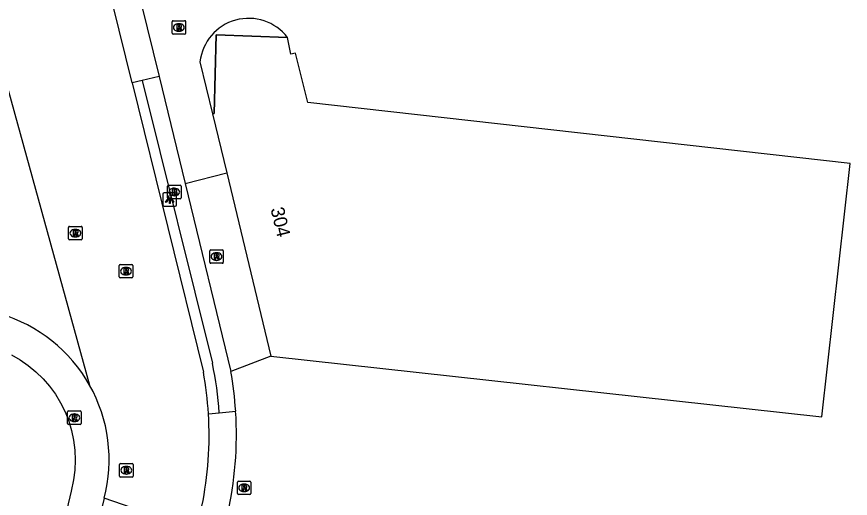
# Model space of a CAD drawing. Extents: x 161389 to 162585, y 388479 to 389761.
# Drawn here: x 162212.3 to 162273.9, y 388784.9 to 388820.5 of the extents above; entities that cross this region are included whole.
import ezdxf

# ---------------------------------------------------------------- set-up
doc = ezdxf.new("R2010")
doc.units = 0
for name, color, linetype in [('IMGEO_Berm_groen', 7, 'Continuous'), ('IMGEO_Brandkraan', 7, 'Continuous'), ('IMGEO_Groenvoorziening', 7, 'Continuous'), ('IMGEO_Lichtpunt', 7, 'Continuous'), ('IMGEO_Pand', 7, 'Continuous'), ('IMGEO_Pand_nummerreeks', 7, 'Continuous'), ('IMGEO_Pand_overbouw', 7, 'Continuous'), ('IMGEO_Rijbaan_lokaal_gesloten', 7, 'Continuous'), ('IMGEO_Rioolput', 7, 'Continuous'), ('IMGEO_Voetpad_open', 7, 'Continuous')]:
    doc.layers.add(name, color=color, linetype=linetype)

msp = doc.modelspace()

# ---------------------------------------------------------------- linework, layer by layer
at = {"layer": 'IMGEO_Berm_groen'}
msp.add_lwpolyline([(162211.87, 388795.491), (162212.509, 388795.125), (162213.115, 388794.707), (162213.682, 388794.24), (162214.21, 388793.725), (162214.692, 388793.168), (162215.126, 388792.573), (162215.506, 388791.944), (162215.833, 388791.284), (162216.104, 388790.598), (162216.315, 388789.895), (162216.466, 388789.173), (162216.556, 388788.442), (162216.584, 388787.707), (162216.55, 388786.972), (162216.453, 388786.242), (162216.273, 388785.418), (162206.891, 388745.858)], dxfattribs=at)
at = {"layer": 'IMGEO_Brandkraan'}
for p, q in [((162223.401, 388807.095), (162223.401, 388807.947)), ((162223.476, 388808.021), (162224.328, 388808.021)), ((162223.889, 388807.801), (162223.914, 388807.801)), ((162224.402, 388807.947), (162224.402, 388807.095)), ((162223.912, 388807.241), (162223.887, 388807.241)), ((162224.328, 388807.021), (162223.476, 388807.021))]:
    msp.add_line(p, q, dxfattribs=at)
for points in [[(162223.401, 388807.095), (162223.401, 388807.947)], [(162223.476, 388808.021), (162224.328, 388808.021)], [(162224.402, 388807.947), (162224.402, 388807.095)], [(162223.749, 388807.721), (162223.749, 388807.321), (162223.962, 388807.321)], [(162223.98, 388807.721), (162223.749, 388807.721)], [(162223.928, 388807.64), (162223.874, 388807.64), (162223.874, 388807.564)], [(162223.874, 388807.564), (162223.927, 388807.564)], [(162223.936, 388807.488), (162223.874, 388807.488), (162223.874, 388807.407)], [(162223.874, 388807.407), (162223.936, 388807.407)], [(162224.328, 388807.021), (162223.476, 388807.021)]]:
    msp.add_lwpolyline(points, dxfattribs=at)
for centre, radius, start, end in [((162223.478, 388807.945), 0.0765, 91.55205, 178.44795), ((162223.478, 388807.945), 0.0765, 91.55205, 178.44795), ((162224.326, 388807.945), 0.0765, 1.55205, 88.44795), ((162224.326, 388807.945), 0.0765, 1.55205, 88.44795), ((162223.929, 388807.602), 0.0379, 267.82845, 90.93552), ((162223.937, 388807.447), 0.0404, 269.87594, 90.50774), ((162223.968, 388807.572), 0.251, 268.66757, 293.53466), ((162223.984, 388807.576), 0.145, 59.4692, 91.53667), ((162224.009, 388807.623), 0.0922, 285.51372, 58.15012), ((162224.014, 388807.431), 0.105, 301.31148, 78.98903), ((162223.478, 388807.097), 0.0765, 181.55205, 268.44795), ((162223.478, 388807.097), 0.0765, 181.55205, 268.44795), ((162224.326, 388807.097), 0.0765, 271.55205, 358.44795), ((162224.326, 388807.097), 0.0765, 271.55205, 358.44795)]:
    msp.add_arc(centre, radius, start, end, dxfattribs=at)
for centre, major_axis, ratio, start_param, end_param in [((162223.888, 388807.521), (-0.387, 0.002), 0.722429, 4.712389, 7.853982), ((162223.913, 388807.521), (-0.39, 0.002), 0.717154, 1.570796, 4.712389)]:
    msp.add_ellipse(centre, major_axis=major_axis, ratio=ratio, start_param=start_param, end_param=end_param, dxfattribs=at)
at = {"layer": 'IMGEO_Groenvoorziening'}
for points in [[(162224.711, 388808.14), (162227.776, 388808.939)], [(162231.038, 388795.401), (162228.092, 388794.265)]]:
    msp.add_lwpolyline(points, dxfattribs=at)
at = {"layer": 'IMGEO_Lichtpunt'}
for p, q in [((162223.066, 388807.368), (162223.066, 388806.561)), ((162223.066, 388807.368), (162223.066, 388806.561)), ((162223.968, 388807.463), (162223.16, 388807.463)), ((162223.968, 388807.463), (162223.16, 388807.463)), ((162224.062, 388806.561), (162224.062, 388807.368)), ((162224.062, 388806.561), (162224.062, 388807.368)), ((162223.16, 388806.467), (162223.968, 388806.467)), ((162223.16, 388806.467), (162223.968, 388806.467))]:
    msp.add_line(p, q, dxfattribs=at)
for points in [[(162223.44, 388807.032), (162223.479, 388807.004), (162223.291, 388806.742), (162223.253, 388806.769), (162223.44, 388807.032)], [(162223.542, 388806.984), (162223.589, 388806.984), (162223.589, 388806.662), (162223.542, 388806.662), (162223.542, 388806.984)], [(162223.652, 388807.004), (162223.69, 388807.031), (162223.877, 388806.769), (162223.838, 388806.741), (162223.652, 388807.004)]]:
    msp.add_lwpolyline(points, dxfattribs=at)
msp.add_circle((162223.565, 388807.166), 0.0994, dxfattribs=at)
for centre, start, end in [((162223.16, 388807.368), 90, 180), ((162223.16, 388807.368), 90, 180), ((162223.968, 388807.368), 0, 90), ((162223.968, 388807.368), 0, 90), ((162223.16, 388806.561), 180, 270), ((162223.16, 388806.561), 180, 270), ((162223.968, 388806.561), 270, 0), ((162223.968, 388806.561), 270, 360)]:
    msp.add_arc(centre, 0.0946, start, end, dxfattribs=at)
at = {"layer": 'IMGEO_Pand'}
for points in [[(162231.038, 388795.401), (162271.748, 388790.899), (162273.864, 388809.635), (162233.763, 388814.128), (162232.868, 388817.788), (162232.528, 388817.705), (162232.274, 388818.939), (162227.004, 388819.135), (162226.862, 388813.333), (162226.729, 388813.284), (162227.776, 388808.939)], [(162227.776, 388808.939), (162231.038, 388795.401)]]:
    msp.add_lwpolyline(points, dxfattribs=at)
at = {"layer": 'IMGEO_Pand_overbouw'}
for points in [[(162225.799, 388817.143), (162226.729, 388813.284), (162226.862, 388813.333), (162227.004, 388819.135)], [(162227.004, 388819.135), (162232.274, 388818.939)]]:
    msp.add_lwpolyline(points, dxfattribs=at)
msp.add_arc((162229.401, 388816.727), 3.626, 37.5972, 173.40812, dxfattribs=at)
at = {"layer": 'IMGEO_Rijbaan_lokaal_gesloten'}
for points in [[(162220.786, 388815.583), (162216.475, 388833.075)], [(162211.175, 388816.678), (162217.643, 388793.25)], [(162220.786, 388815.583), (162226.052, 388794.217)], [(162218.716, 388784.885), (162218.423, 388783.692), (162213.659, 388764.62), (162209.992, 388750), (162203.693, 388724.874), (162198.604, 388704.506), (162198.376, 388703.539)], [(162225.506, 388782.552), (162218.716, 388784.885)]]:
    msp.add_lwpolyline(points, dxfattribs=at)
for centre, radius, start, end in [((162207.858, 388787.74), 11.229, 29.384, 73.49797), ((162200.717, 388789.555), 25.76, 3.51212, 10.42684), ((162207.862, 388787.744), 11.225, 345.24381, 29.37532), ((162200.611, 388789.538), 25.868, 348.32437, 3.5354)]:
    msp.add_arc(centre, radius, start, end, dxfattribs=at)
at = {"layer": 'IMGEO_Rioolput'}
for p, q in [((162223.818, 388820.178), (162224.67, 388820.178)), ((162223.743, 388819.252), (162223.743, 388820.104)), ((162224.231, 388819.958), (162224.256, 388819.958)), ((162224.744, 388820.104), (162224.744, 388819.252)), ((162224.67, 388819.178), (162223.818, 388819.178)), ((162224.254, 388819.398), (162224.229, 388819.398)), ((162216.096, 388804.055), (162216.096, 388804.907)), ((162216.171, 388804.981), (162217.023, 388804.981)), ((162216.584, 388804.761), (162216.609, 388804.761)), ((162217.097, 388804.907), (162217.097, 388804.055)), ((162216.607, 388804.201), (162216.582, 388804.201)), ((162217.023, 388803.981), (162216.171, 388803.981)), ((162226.525, 388802.324), (162226.525, 388803.176)), ((162226.6, 388803.25), (162227.452, 388803.25)), ((162227.013, 388803.03), (162227.038, 388803.03)), ((162227.526, 388803.176), (162227.526, 388802.324)), ((162227.452, 388802.25), (162226.6, 388802.25)), ((162227.036, 388802.47), (162227.011, 388802.47)), ((162219.838, 388801.244), (162219.838, 388802.096)), ((162219.913, 388802.17), (162220.765, 388802.17)), ((162220.326, 388801.95), (162220.351, 388801.95)), ((162220.839, 388802.096), (162220.839, 388801.244)), ((162220.765, 388801.17), (162219.913, 388801.17)), ((162220.349, 388801.39), (162220.324, 388801.39)), ((162216.021, 388790.414), (162216.021, 388791.266)), ((162216.096, 388791.34), (162216.948, 388791.34)), ((162217.022, 388791.266), (162217.022, 388790.414)), ((162216.532, 388790.56), (162216.507, 388790.56)), ((162216.509, 388791.12), (162216.534, 388791.12)), ((162216.948, 388790.34), (162216.096, 388790.34)), ((162219.932, 388787.46), (162220.784, 388787.46)), ((162219.857, 388786.534), (162219.857, 388787.386)), ((162220.345, 388787.24), (162220.37, 388787.24)), ((162220.858, 388787.386), (162220.858, 388786.534)), ((162220.784, 388786.46), (162219.932, 388786.46)), ((162220.368, 388786.68), (162220.343, 388786.68)), ((162228.567, 388785.234), (162228.567, 388786.086)), ((162228.642, 388786.16), (162229.494, 388786.16)), ((162229.055, 388785.94), (162229.08, 388785.94)), ((162229.568, 388786.086), (162229.568, 388785.234)), ((162229.494, 388785.16), (162228.642, 388785.16)), ((162229.078, 388785.38), (162229.053, 388785.38))]:
    msp.add_line(p, q, dxfattribs=at)
for points in [[(162223.818, 388820.178), (162224.67, 388820.178)], [(162223.743, 388819.252), (162223.743, 388820.104)], [(162224.332, 388819.876), (162224.08, 388819.878), (162224.08, 388819.478)], [(162224.08, 388819.478), (162224.204, 388819.478), (162224.204, 388819.64), (162224.215, 388819.64)], [(162224.258, 388819.797), (162224.204, 388819.797), (162224.204, 388819.716)], [(162224.204, 388819.716), (162224.256, 388819.716)], [(162224.262, 388819.611), (162224.333, 388819.478), (162224.473, 388819.478), (162224.408, 388819.604)], [(162224.744, 388820.104), (162224.744, 388819.252)], [(162224.67, 388819.178), (162223.818, 388819.178)], [(162216.096, 388804.055), (162216.096, 388804.907)], [(162216.171, 388804.981), (162217.023, 388804.981)], [(162217.097, 388804.907), (162217.097, 388804.055)], [(162216.685, 388804.679), (162216.433, 388804.681), (162216.433, 388804.281)], [(162216.433, 388804.281), (162216.557, 388804.281), (162216.557, 388804.443), (162216.568, 388804.443)], [(162216.611, 388804.6), (162216.557, 388804.6), (162216.557, 388804.519)], [(162216.557, 388804.519), (162216.609, 388804.519)], [(162216.615, 388804.414), (162216.686, 388804.281), (162216.826, 388804.281), (162216.761, 388804.407)], [(162217.023, 388803.981), (162216.171, 388803.981)], [(162226.525, 388802.324), (162226.525, 388803.176)], [(162226.6, 388803.25), (162227.452, 388803.25)], [(162227.114, 388802.948), (162226.862, 388802.95), (162226.862, 388802.55)], [(162227.04, 388802.869), (162226.986, 388802.869), (162226.986, 388802.788)], [(162227.526, 388803.176), (162227.526, 388802.324)], [(162227.452, 388802.25), (162226.6, 388802.25)], [(162226.862, 388802.55), (162226.986, 388802.55), (162226.986, 388802.712), (162226.997, 388802.712)], [(162226.986, 388802.788), (162227.038, 388802.788)], [(162227.044, 388802.683), (162227.115, 388802.55), (162227.255, 388802.55), (162227.19, 388802.676)], [(162219.838, 388801.244), (162219.838, 388802.096)], [(162219.913, 388802.17), (162220.765, 388802.17)], [(162220.427, 388801.868), (162220.175, 388801.87), (162220.175, 388801.47)], [(162220.175, 388801.47), (162220.299, 388801.47), (162220.299, 388801.632), (162220.31, 388801.632)], [(162220.353, 388801.789), (162220.299, 388801.789), (162220.299, 388801.708)], [(162220.299, 388801.708), (162220.351, 388801.708)], [(162220.839, 388802.096), (162220.839, 388801.244)], [(162220.765, 388801.17), (162219.913, 388801.17)], [(162220.357, 388801.603), (162220.428, 388801.47), (162220.568, 388801.47), (162220.503, 388801.596)], [(162216.021, 388790.414), (162216.021, 388791.266)], [(162216.096, 388791.34), (162216.948, 388791.34)], [(162217.022, 388791.266), (162217.022, 388790.414)], [(162216.61, 388791.038), (162216.358, 388791.04), (162216.358, 388790.64)], [(162216.358, 388790.64), (162216.482, 388790.64), (162216.482, 388790.802), (162216.493, 388790.802)], [(162216.536, 388790.959), (162216.482, 388790.959), (162216.482, 388790.878)], [(162216.482, 388790.878), (162216.534, 388790.878)], [(162216.54, 388790.773), (162216.611, 388790.64), (162216.751, 388790.64), (162216.686, 388790.766)], [(162216.948, 388790.34), (162216.096, 388790.34)], [(162219.932, 388787.46), (162220.784, 388787.46)], [(162219.857, 388786.534), (162219.857, 388787.386)], [(162220.446, 388787.158), (162220.194, 388787.16), (162220.194, 388786.76)], [(162220.194, 388786.76), (162220.318, 388786.76), (162220.318, 388786.922), (162220.329, 388786.922)], [(162220.372, 388787.079), (162220.318, 388787.079), (162220.318, 388786.998)], [(162220.318, 388786.998), (162220.37, 388786.998)], [(162220.376, 388786.893), (162220.447, 388786.76), (162220.587, 388786.76), (162220.522, 388786.886)], [(162220.858, 388787.386), (162220.858, 388786.534)], [(162220.784, 388786.46), (162219.932, 388786.46)], [(162228.567, 388785.234), (162228.567, 388786.086)], [(162228.642, 388786.16), (162229.494, 388786.16)], [(162229.156, 388785.858), (162228.904, 388785.86), (162228.904, 388785.46)], [(162228.904, 388785.46), (162229.028, 388785.46), (162229.028, 388785.622), (162229.039, 388785.622)], [(162229.082, 388785.779), (162229.028, 388785.779), (162229.028, 388785.698)], [(162229.028, 388785.698), (162229.08, 388785.698)], [(162229.568, 388786.086), (162229.568, 388785.234)], [(162229.494, 388785.16), (162228.642, 388785.16)], [(162229.086, 388785.593), (162229.157, 388785.46), (162229.297, 388785.46), (162229.232, 388785.586)]]:
    msp.add_lwpolyline(points, dxfattribs=at)
for centre, radius, start, end in [((162223.82, 388820.102), 0.0765, 91.55205, 178.44795), ((162223.82, 388820.102), 0.0765, 91.55205, 178.44795), ((162224.668, 388820.102), 0.0765, 1.55205, 88.44795), ((162224.668, 388820.102), 0.0765, 1.55205, 88.44795), ((162224.214, 388819.587), 0.0533, 26.02933, 88.69889), ((162224.24, 388819.905), 0.19, 274.7715, 282.96867), ((162224.264, 388819.701), 0.0964, 77.00612, 93.18647), ((162224.278, 388819.758), 0.0378, 276.66336, 79.67722), ((162224.331, 388819.766), 0.109, 350.36119, 89.41601), ((162224.329, 388819.766), 0.112, 277.58423, 350.98172), ((162224.313, 388819.551), 0.108, 29.51342, 73.79051), ((162223.82, 388819.254), 0.0765, 181.55205, 268.44795), ((162223.82, 388819.254), 0.0765, 181.55205, 268.44795), ((162224.668, 388819.254), 0.0765, 271.55205, 358.44795), ((162224.668, 388819.254), 0.0765, 271.55205, 358.44795), ((162216.173, 388804.905), 0.0765, 91.55205, 178.44795), ((162216.173, 388804.905), 0.0765, 91.55205, 178.44795), ((162217.021, 388804.905), 0.0765, 1.55205, 88.44795), ((162217.021, 388804.905), 0.0765, 1.55205, 88.44795), ((162216.567, 388804.39), 0.0533, 26.02933, 88.69889), ((162216.593, 388804.708), 0.19, 274.7715, 282.96867), ((162216.617, 388804.504), 0.0964, 77.00612, 93.18647), ((162216.631, 388804.561), 0.0378, 276.66336, 79.67722), ((162216.684, 388804.569), 0.109, 350.36119, 89.41601), ((162216.682, 388804.569), 0.112, 277.58423, 350.98172), ((162216.666, 388804.354), 0.108, 29.51342, 73.79051), ((162216.173, 388804.057), 0.0765, 181.55205, 268.44795), ((162216.173, 388804.057), 0.0765, 181.55205, 268.44795), ((162217.021, 388804.057), 0.0765, 271.55205, 358.44795), ((162217.021, 388804.057), 0.0765, 271.55205, 358.44795), ((162226.602, 388803.174), 0.0765, 91.55205, 178.44795), ((162226.602, 388803.174), 0.0765, 91.55205, 178.44795), ((162227.046, 388802.773), 0.0964, 77.00612, 93.18647), ((162227.06, 388802.83), 0.0378, 276.66336, 79.67722), ((162227.113, 388802.838), 0.109, 350.36119, 89.41601), ((162227.45, 388803.174), 0.0765, 1.55205, 88.44795), ((162227.45, 388803.174), 0.0765, 1.55205, 88.44795), ((162226.602, 388802.326), 0.0765, 181.55205, 268.44795), ((162226.602, 388802.326), 0.0765, 181.55205, 268.44795), ((162226.996, 388802.659), 0.0533, 26.02933, 88.69889), ((162227.022, 388802.977), 0.19, 274.7715, 282.96867), ((162227.111, 388802.838), 0.112, 277.58423, 350.98172), ((162227.095, 388802.623), 0.108, 29.51342, 73.79051), ((162227.45, 388802.326), 0.0765, 271.55205, 358.44795), ((162227.45, 388802.326), 0.0765, 271.55205, 358.44795), ((162219.915, 388802.094), 0.0765, 91.55205, 178.44795), ((162219.915, 388802.094), 0.0765, 91.55205, 178.44795), ((162220.309, 388801.579), 0.0533, 26.02933, 88.69889), ((162220.335, 388801.897), 0.19, 274.7715, 282.96867), ((162220.359, 388801.693), 0.0964, 77.00612, 93.18647), ((162220.373, 388801.75), 0.0378, 276.66336, 79.67722), ((162220.426, 388801.758), 0.109, 350.36119, 89.41601), ((162220.424, 388801.758), 0.112, 277.58423, 350.98172), ((162220.408, 388801.543), 0.108, 29.51342, 73.79051), ((162220.763, 388802.094), 0.0765, 1.55205, 88.44795), ((162220.763, 388802.094), 0.0765, 1.55205, 88.44795), ((162219.915, 388801.246), 0.0765, 181.55205, 268.44795), ((162219.915, 388801.246), 0.0765, 181.55205, 268.44795), ((162220.763, 388801.246), 0.0765, 271.55205, 358.44795), ((162220.763, 388801.246), 0.0765, 271.55205, 358.44795), ((162216.098, 388791.264), 0.0765, 91.55205, 178.44795), ((162216.098, 388791.264), 0.0765, 91.55205, 178.44795), ((162216.946, 388791.264), 0.0765, 1.55205, 88.44795), ((162216.946, 388791.264), 0.0765, 1.55205, 88.44795), ((162216.492, 388790.749), 0.0533, 26.02933, 88.69889), ((162216.518, 388791.067), 0.19, 274.7715, 282.96867), ((162216.542, 388790.863), 0.0964, 77.00612, 93.18647), ((162216.556, 388790.92), 0.0378, 276.66336, 79.67722), ((162216.609, 388790.928), 0.109, 350.36119, 89.41601), ((162216.607, 388790.928), 0.112, 277.58423, 350.98172), ((162216.591, 388790.713), 0.108, 29.51342, 73.79051), ((162216.098, 388790.416), 0.0765, 181.55205, 268.44795), ((162216.098, 388790.416), 0.0765, 181.55205, 268.44795), ((162216.946, 388790.416), 0.0765, 271.55205, 358.44795), ((162216.946, 388790.416), 0.0765, 271.55205, 358.44795), ((162219.934, 388787.384), 0.0765, 91.55205, 178.44795), ((162219.934, 388787.384), 0.0765, 91.55205, 178.44795), ((162220.782, 388787.384), 0.0765, 1.55205, 88.44795), ((162220.782, 388787.384), 0.0765, 1.55205, 88.44795), ((162220.328, 388786.869), 0.0533, 26.02933, 88.69889), ((162220.354, 388787.187), 0.19, 274.7715, 282.96867), ((162220.378, 388786.983), 0.0964, 77.00612, 93.18647), ((162220.392, 388787.04), 0.0378, 276.66336, 79.67722), ((162220.445, 388787.048), 0.109, 350.36119, 89.41601), ((162220.443, 388787.048), 0.112, 277.58423, 350.98172), ((162220.427, 388786.833), 0.108, 29.51342, 73.79051), ((162219.934, 388786.536), 0.0765, 181.55205, 268.44795), ((162219.934, 388786.536), 0.0765, 181.55205, 268.44795), ((162220.782, 388786.536), 0.0765, 271.55205, 358.44795), ((162220.782, 388786.536), 0.0765, 271.55205, 358.44795), ((162228.644, 388786.084), 0.0765, 91.55205, 178.44795), ((162228.644, 388786.084), 0.0765, 91.55205, 178.44795), ((162229.038, 388785.569), 0.0533, 26.02933, 88.69889), ((162229.064, 388785.887), 0.19, 274.7715, 282.96867), ((162229.088, 388785.683), 0.0964, 77.00612, 93.18647), ((162229.102, 388785.74), 0.0378, 276.66336, 79.67722), ((162229.155, 388785.748), 0.109, 350.36119, 89.41601), ((162229.153, 388785.748), 0.112, 277.58423, 350.98172), ((162229.137, 388785.533), 0.108, 29.51342, 73.79051), ((162229.492, 388786.084), 0.0765, 1.55205, 88.44795), ((162229.492, 388786.084), 0.0765, 1.55205, 88.44795), ((162228.644, 388785.236), 0.0765, 181.55205, 268.44795), ((162228.644, 388785.236), 0.0765, 181.55205, 268.44795), ((162229.492, 388785.236), 0.0765, 271.55205, 358.44795), ((162229.492, 388785.236), 0.0765, 271.55205, 358.44795)]:
    msp.add_arc(centre, radius, start, end, dxfattribs=at)
for centre, major_axis, ratio, start_param, end_param in [((162224.23, 388819.678), (-0.387, 0.002), 0.722429, 4.712389, 7.853982), ((162224.255, 388819.678), (-0.39, 0.002), 0.717154, 1.570796, 4.712389), ((162216.583, 388804.481), (-0.387, 0.002), 0.722429, 4.712389, 7.853982), ((162216.608, 388804.481), (-0.39, 0.002), 0.717154, 1.570796, 4.712389), ((162227.012, 388802.75), (-0.387, 0.002), 0.722429, 4.712389, 7.853982), ((162227.037, 388802.75), (-0.39, 0.002), 0.717154, 1.570796, 4.712389), ((162220.325, 388801.67), (-0.387, 0.002), 0.722429, 4.712389, 7.853982), ((162220.35, 388801.67), (-0.39, 0.002), 0.717154, 1.570796, 4.712389), ((162216.508, 388790.84), (-0.387, 0.002), 0.722429, 4.712389, 7.853982), ((162216.533, 388790.84), (-0.39, 0.002), 0.717154, 1.570796, 4.712389), ((162220.344, 388786.96), (-0.387, 0.002), 0.722429, 4.712389, 7.853982), ((162220.369, 388786.96), (-0.39, 0.002), 0.717154, 1.570796, 4.712389), ((162229.054, 388785.66), (-0.387, 0.002), 0.722429, 4.712389, 7.853982), ((162229.079, 388785.66), (-0.39, 0.002), 0.717154, 1.570796, 4.712389)]:
    msp.add_ellipse(centre, major_axis=major_axis, ratio=ratio, start_param=start_param, end_param=end_param, dxfattribs=at)
at = {"layer": 'IMGEO_Voetpad_open'}
for points in [[(162220.139, 388826.772), (162222.783, 388816.053)], [(162222.783, 388816.053), (162221.534, 388815.762)], [(162222.783, 388816.053), (162224.711, 388808.14)], [(162221.534, 388815.762), (162220.786, 388815.583)], [(162221.534, 388815.762), (162226.72, 388794.861)], [(162224.711, 388808.14), (162228.092, 388794.265)], [(162226.429, 388791.133), (162227.227, 388791.205)], [(162227.227, 388791.205), (162228.44, 388791.315)]]:
    msp.add_lwpolyline(points, dxfattribs=at)
for centre, radius, start, end in [((162200.705, 388789.39), 26.585, 3.91454, 11.87587), ((162201.113, 388789.587), 27.382, 3.61852, 9.83721), ((162201.265, 388789.602), 27.228, 347.2353, 3.60684)]:
    msp.add_arc(centre, radius, start, end, dxfattribs=at)

# ---------------------------------------------------------------- texts
at = {"layer": 'IMGEO_Pand_nummerreeks'}
msp.add_text('304', height=1, rotation=283.55024, dxfattribs=at).set_placement((162231.011, 388806.273))

doc.saveas('drawing.dxf')
